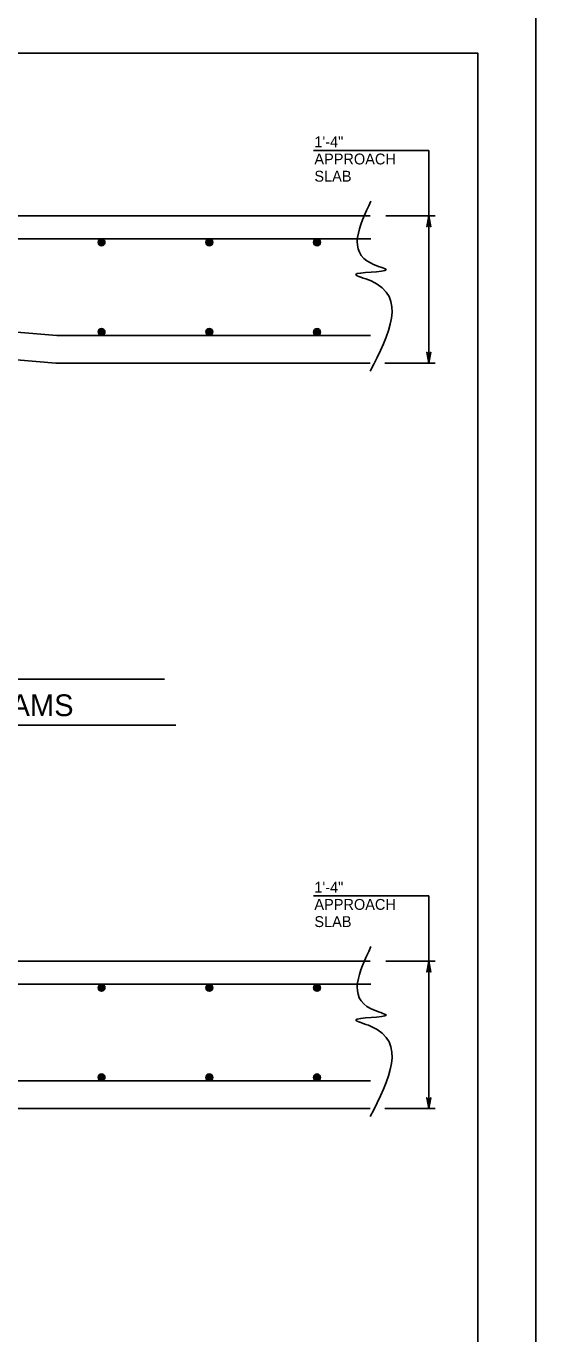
# Model space of a CAD drawing. Extents: x 638079 to 640019, y 297691 to 298879.
# Drawn here: x 638974.3 to 639115, y 297916.6 to 298277.7 of the extents above; entities that cross this region are included whole.
import ezdxf

# ---------------------------------------------------------------- set-up
doc = ezdxf.new("R2010")
doc.units = 0
doc.layers.add('1', color=7, linetype='Continuous')
doc.layers.add('PLT-BNDY', color=7, linetype='Continuous')

msp = doc.modelspace()

# ---------------------------------------------------------------- linework, layer by layer
at = {"layer": '1'}
for p, q in [((639053.59, 298243.41), (639085.46, 298243.41)), ((639085.46, 298184.69), (639085.46, 298243.41)), ((638838.63, 298225.33), (639069.29, 298225.33)), ((639073.62, 298225.33), (639087.21, 298225.33)), ((638931.34, 298218.98), (639069.48, 298218.98)), ((638860.54, 298194.85), (638982.45, 298184.69)), ((638929.95, 298196.72), (638982.77, 298192.31)), ((638982.77, 298192.31), (639069.36, 298192.31)), ((638982.45, 298184.69), (639069.29, 298184.69)), ((639073.3, 298184.69), (639087.21, 298184.69)), ((638842.97, 298097.37), (639012.44, 298097.37)), ((638839.65, 298084.73), (639015.56, 298084.73)), ((639053.59, 298037.58), (639085.46, 298037.58)), ((639085.46, 297978.86), (639085.46, 298037.58)), ((638838.63, 298019.5), (639069.29, 298019.5)), ((639073.62, 298019.5), (639087.21, 298019.5)), ((638931.34, 298013.15), (639069.48, 298013.15)), ((638931.34, 297986.48), (639069.36, 297986.48)), ((638906.26, 297978.86), (639069.29, 297978.86)), ((639073.3, 297978.86), (639087.21, 297978.86))]:
    msp.add_line(p, q, dxfattribs=at)
for points in [[(639099.03, 297706.23), (639099.03, 298270.23), (638313.03, 298270.23), (638313.03, 297706.23), (639099.03, 297706.23), (639099.03, 297732.59), (638899.03, 297732.59), (638899.03, 297797.26), (639099.03, 297797.26), (639099.03, 297826.23), (638899.03, 297826.23), (638899.03, 297706.23), (638977.83, 297706.23), (638977.83, 297732.59), (638977.83, 297706.23), (639054.83, 297706.23), (639054.83, 297732.59), (639054.83, 297720.27), (639099.03, 297720.27)], [(639085.46, 298225.33), (639086.02, 298222.35), (639085.94, 298222.46), (639085.86, 298222.58), (639085.76, 298222.64), (639085.66, 298222.7), (639085.56, 298222.72), (639085.46, 298222.73), (639085.36, 298222.72), (639085.26, 298222.7), (639085.16, 298222.64), (639085.06, 298222.58), (639084.98, 298222.46), (639084.9, 298222.35), (639085.46, 298225.33), (639084.98, 298222.46), (639085.06, 298222.58), (639085.46, 298225.33), (639085.16, 298222.64), (639085.26, 298222.7), (639085.46, 298225.33), (639085.36, 298222.72), (639085.46, 298222.73), (639085.46, 298225.33), (639085.56, 298222.72), (639085.66, 298222.7), (639085.46, 298225.33), (639085.76, 298222.64), (639085.86, 298222.58), (639085.46, 298225.33), (639085.94, 298222.46)], [(639085.46, 298184.69), (639084.9, 298187.68), (639084.98, 298187.56), (639085.06, 298187.45), (639085.16, 298187.39), (639085.26, 298187.33), (639085.36, 298187.31), (639085.46, 298187.29), (639085.56, 298187.31), (639085.66, 298187.33), (639085.76, 298187.39), (639085.86, 298187.45), (639085.94, 298187.56), (639086.02, 298187.68), (639085.46, 298184.69), (639085.94, 298187.56), (639085.86, 298187.45), (639085.46, 298184.69), (639085.76, 298187.39), (639085.66, 298187.33), (639085.46, 298184.69), (639085.56, 298187.31), (639085.46, 298187.29), (639085.46, 298184.69), (639085.36, 298187.31), (639085.26, 298187.33), (639085.46, 298184.69), (639085.16, 298187.39), (639085.06, 298187.45), (639085.46, 298184.69), (639084.98, 298187.56)], [(639085.46, 298019.5), (639086.02, 298016.51), (639085.94, 298016.63), (639085.86, 298016.74), (639085.76, 298016.8), (639085.66, 298016.86), (639085.56, 298016.88), (639085.46, 298016.9), (639085.36, 298016.88), (639085.26, 298016.86), (639085.16, 298016.8), (639085.06, 298016.74), (639084.98, 298016.63), (639084.9, 298016.51), (639085.46, 298019.5), (639084.98, 298016.63), (639085.06, 298016.74), (639085.46, 298019.5), (639085.16, 298016.8), (639085.26, 298016.86), (639085.46, 298019.5), (639085.36, 298016.88), (639085.46, 298016.9), (639085.46, 298019.5), (639085.56, 298016.88), (639085.66, 298016.86), (639085.46, 298019.5), (639085.76, 298016.8), (639085.86, 298016.74), (639085.46, 298019.5), (639085.94, 298016.63)], [(639085.46, 297978.86), (639084.9, 297981.84), (639084.98, 297981.73), (639085.06, 297981.61), (639085.16, 297981.55), (639085.26, 297981.49), (639085.36, 297981.48), (639085.46, 297981.46), (639085.56, 297981.48), (639085.66, 297981.49), (639085.76, 297981.55), (639085.86, 297981.61), (639085.94, 297981.73), (639086.02, 297981.84), (639085.46, 297978.86), (639085.94, 297981.73), (639085.86, 297981.61), (639085.46, 297978.86), (639085.76, 297981.55), (639085.66, 297981.49), (639085.46, 297978.86), (639085.56, 297981.48), (639085.46, 297981.46), (639085.46, 297978.86), (639085.36, 297981.48), (639085.26, 297981.49), (639085.46, 297978.86), (639085.16, 297981.55), (639085.06, 297981.61), (639085.46, 297978.86), (639084.98, 297981.73)]]:
    msp.add_lwpolyline(points, dxfattribs=at)
for centre, radius in [((638995.07, 298218.03), 0.952), ((638995.07, 298218.03), 0.714), ((638995.07, 298218.03), 0.476), ((638995.07, 298218.03), 0.238), ((639024.84, 298218.03), 0.952), ((639024.84, 298218.03), 0.714), ((639024.84, 298218.03), 0.476), ((639024.84, 298218.03), 0.238), ((639054.6, 298218.03), 0.952), ((639054.6, 298218.03), 0.714), ((639054.6, 298218.03), 0.476), ((639054.6, 298218.03), 0.238), ((638995.07, 298193.29), 0.952), ((638995.07, 298193.29), 0.714), ((638995.07, 298193.29), 0.476), ((638995.07, 298193.29), 0.238), ((639024.84, 298193.29), 0.952), ((639024.84, 298193.29), 0.714), ((639024.84, 298193.29), 0.476), ((639024.84, 298193.29), 0.238), ((639054.6, 298193.26), 0.952), ((639054.6, 298193.26), 0.714), ((639054.6, 298193.26), 0.476), ((639054.6, 298193.26), 0.238), ((638995.07, 298012.2), 0.952), ((638995.07, 298012.2), 0.714), ((638995.07, 298012.2), 0.476), ((638995.07, 298012.2), 0.238), ((639024.84, 298012.2), 0.952), ((639024.84, 298012.2), 0.714), ((639024.84, 298012.2), 0.476), ((639024.84, 298012.2), 0.238), ((639054.6, 298012.2), 0.952), ((639054.6, 298012.2), 0.714), ((639054.6, 298012.2), 0.476), ((639054.6, 298012.2), 0.238), ((638995.07, 297987.46), 0.952), ((638995.07, 297987.46), 0.714), ((638995.07, 297987.46), 0.476), ((638995.07, 297987.46), 0.238), ((639024.84, 297987.45), 0.952), ((639024.84, 297987.45), 0.714), ((639024.84, 297987.45), 0.476), ((639024.84, 297987.45), 0.238), ((639054.6, 297987.43), 0.952), ((639054.6, 297987.43), 0.714), ((639054.6, 297987.43), 0.476), ((639054.6, 297987.43), 0.238)]:
    msp.add_circle(centre, radius, dxfattribs=at)
for points in [[(639069.29, 298182.43), (639069.51, 298207.36), (639065.34, 298209.15), (639073.67, 298210.45), (639069.51, 298212.24), (639069.48, 298229.4)], [(639069.29, 297976.6), (639069.51, 298001.53), (639065.34, 298003.31), (639073.67, 298004.62), (639069.51, 298006.4), (639069.48, 298023.56)]]:
    msp.add_spline(points, degree=3, dxfattribs=at)
at = {"layer": 'PLT-BNDY'}
msp.add_lwpolyline([(638274.03, 298285.23), (639115.03, 298285.23), (639115.03, 297691.23), (638274.03, 297691.23)], close=True, dxfattribs=at)

# ---------------------------------------------------------------- texts
at = {"layer": '1'}
for s, height, p in [('1\'-4"', 3, (639053.86, 298244.29)), ('APPROACH', 3, (639053.86, 298239.54)), ('SLAB', 3, (639053.86, 298234.79)), ('ADJACENT COMPOSITE BOX BEAMS ', 6, (638845.13, 298087.2)), ('1\'-4"', 3, (639053.86, 298038.45)), ('APPROACH', 3, (639053.86, 298033.71)), ('SLAB', 3, (639053.86, 298028.96))]:
    msp.add_text(s, height=height, dxfattribs=at).set_placement(p)

doc.saveas('drawing.dxf')
